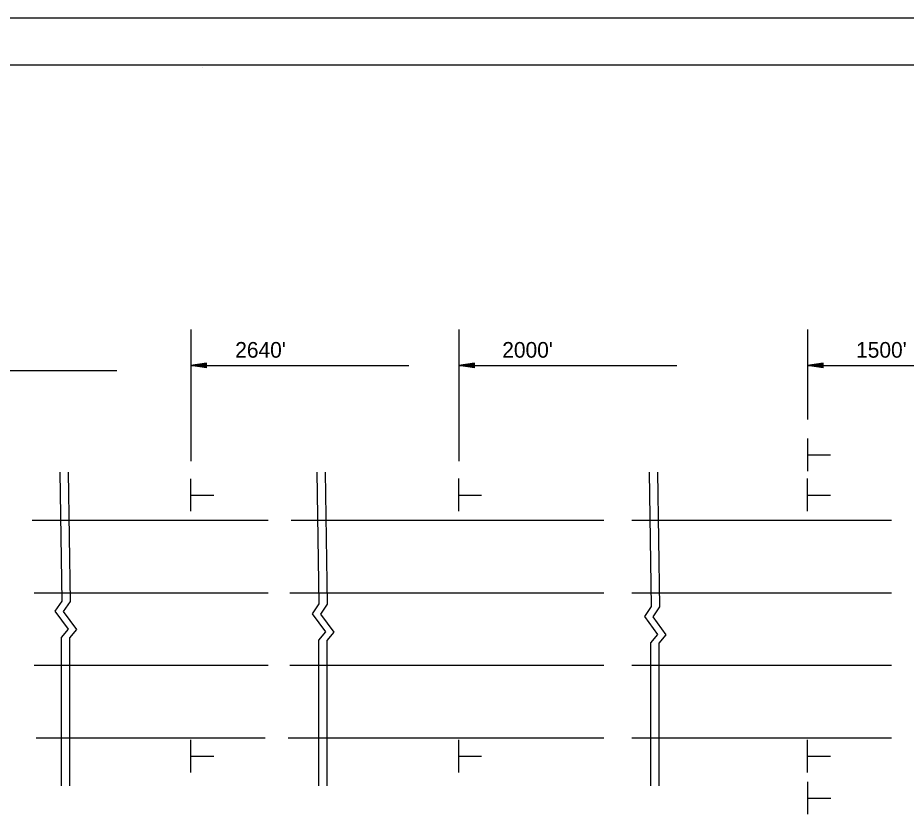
# Model space of a CAD drawing. Extents: x 1397271 to 1411271, y 376395 to 377888.
# Drawn here: x 1402985 to 1403500, y 377424 to 377888 of the extents above; entities that cross this region are included whole.
import ezdxf

# ---------------------------------------------------------------- set-up
doc = ezdxf.new("R2010")
doc.units = 0
for name, color, linetype in [('Default', 7, 'Continuous'), ('R_Border', 7, 'Continuous'), ('R_MOT', 7, 'Continuous'), ('R_No Plot', 7, 'Continuous')]:
    doc.layers.add(name, color=color, linetype=linetype)

msp = doc.modelspace()

# ---------------------------------------------------------------- linework, layer by layer
at = {"layer": 'Default'}
for p, q in [((1403085.35, 377707.31), (1403085.35, 377631.08)), ((1403240.48, 377707.31), (1403240.48, 377631.08)), ((1403442.43, 377707.31), (1403442.43, 377655.12)), ((1403094.42, 377687.9), (1403085.35, 377686.54)), ((1403094.42, 377687.67), (1403086.87, 377686.54)), ((1403094.42, 377687.44), (1403088.43, 377686.54)), ((1403094.42, 377687.22), (1403089.94, 377686.54)), ((1403094.42, 377686.98), (1403091.47, 377686.54)), ((1403094.42, 377685.18), (1403094.42, 377687.9)), ((1403249.55, 377687.9), (1403240.48, 377686.54)), ((1403249.55, 377687.67), (1403242, 377686.54)), ((1403249.55, 377687.44), (1403243.56, 377686.54)), ((1403249.55, 377687.22), (1403245.07, 377686.54)), ((1403249.55, 377686.98), (1403246.6, 377686.54)), ((1403249.55, 377685.18), (1403249.55, 377687.9)), ((1403451.5, 377687.9), (1403442.43, 377686.54)), ((1403451.5, 377687.67), (1403443.95, 377686.54)), ((1403451.5, 377687.44), (1403445.51, 377686.54)), ((1403451.5, 377687.22), (1403447.02, 377686.54)), ((1403451.5, 377686.98), (1403448.55, 377686.54)), ((1403451.5, 377685.18), (1403451.5, 377687.9)), ((1402916.19, 377683.64), (1403042.37, 377683.64)), ((1403085.35, 377686.54), (1403211.54, 377686.54)), ((1403094.42, 377685.18), (1403085.35, 377686.54)), ((1403094.42, 377685.41), (1403086.87, 377686.54)), ((1403094.42, 377685.64), (1403088.43, 377686.54)), ((1403094.42, 377685.86), (1403089.94, 377686.54)), ((1403094.42, 377686.1), (1403091.47, 377686.54)), ((1403094.42, 377686.75), (1403092.99, 377686.54)), ((1403094.42, 377686.33), (1403092.99, 377686.54)), ((1403240.48, 377686.54), (1403366.67, 377686.54)), ((1403249.55, 377685.18), (1403240.48, 377686.54)), ((1403249.55, 377685.41), (1403242, 377686.54)), ((1403249.55, 377685.64), (1403243.56, 377686.54)), ((1403249.55, 377685.86), (1403245.07, 377686.54)), ((1403249.55, 377686.1), (1403246.6, 377686.54)), ((1403249.55, 377686.75), (1403248.12, 377686.54)), ((1403249.55, 377686.33), (1403248.12, 377686.54)), ((1403442.43, 377686.54), (1403568.62, 377686.54)), ((1403451.5, 377685.18), (1403442.43, 377686.54)), ((1403451.5, 377685.41), (1403443.95, 377686.54)), ((1403451.5, 377685.64), (1403445.51, 377686.54)), ((1403451.5, 377685.86), (1403447.02, 377686.54)), ((1403451.5, 377686.1), (1403448.55, 377686.54)), ((1403451.5, 377686.75), (1403450.07, 377686.54)), ((1403451.5, 377686.33), (1403450.07, 377686.54)), ((1402993.52, 377596.8), (1403130.05, 377596.8)), ((1403143.36, 377596.8), (1403324.47, 377596.8)), ((1403340.61, 377596.8), (1403491.05, 377596.8)), ((1402994.63, 377554.76), (1403130.05, 377554.76)), ((1403142.54, 377554.76), (1403324.47, 377554.76)), ((1403340.61, 377554.76), (1403491.05, 377554.76)), ((1402994.63, 377512.73), (1403130.05, 377512.73)), ((1403142.54, 377512.73), (1403324.47, 377512.73)), ((1403340.61, 377512.73), (1403491.05, 377512.73)), ((1402995.74, 377470.69), (1403128.42, 377470.69)), ((1403141.73, 377470.69), (1403324.47, 377470.69)), ((1403340.61, 377470.69), (1403491.05, 377470.69))]:
    msp.add_line(p, q, dxfattribs=at)
at = {"layer": 'R_Border'}
for p, q in [((1402024.58, 377860.72), (1404237.88, 377860.72)), ((1403092.23, 377858.9), (1403092.23, 377858.9)), ((1403092.23, 377858.9), (1403092.23, 377858.9))]:
    msp.add_line(p, q, dxfattribs=at)
at = {"layer": 'R_MOT'}
for p, q in [((1403442.48, 377625.33), (1403442.48, 377644.24)), ((1403442.76, 377634.73), (1403455.67, 377634.73)), ((1403085.35, 377601.98), (1403085.35, 377620.89)), ((1403240.48, 377601.98), (1403240.48, 377620.9)), ((1403442.43, 377601.98), (1403442.43, 377620.9)), ((1403085.63, 377611.39), (1403098.54, 377611.39)), ((1403240.76, 377611.39), (1403253.67, 377611.39)), ((1403442.71, 377611.39), (1403455.63, 377611.39)), ((1403085.35, 377450.7), (1403085.35, 377469.62)), ((1403240.48, 377450.7), (1403240.48, 377469.62)), ((1403442.43, 377450.7), (1403442.43, 377469.62)), ((1403085.63, 377460.11), (1403098.54, 377460.11)), ((1403240.76, 377460.11), (1403253.67, 377460.11)), ((1403442.71, 377460.11), (1403455.63, 377460.11)), ((1403442.64, 377426.4), (1403442.64, 377445.31)), ((1403442.92, 377435.8), (1403455.83, 377435.8))]:
    msp.add_line(p, q, dxfattribs=at)
for points in [[(1403009.37, 377624.62), (1403010.51, 377549.98), (1403006.58, 377544.14), (1403014.23, 377533.67), (1403010.2, 377528.84), (1403010.18, 377442.87)], [(1403014.2, 377624.62), (1403015.34, 377549.78), (1403011.41, 377543.94), (1403019.06, 377533.47), (1403015.03, 377528.64), (1403015.02, 377442.87)], [(1403158.3, 377624.62), (1403159.46, 377548.39), (1403155.54, 377542.55), (1403163.19, 377532.09), (1403159.16, 377527.25), (1403159.15, 377442.87)], [(1403163.13, 377624.62), (1403164.29, 377548.19), (1403160.37, 377542.35), (1403168.02, 377531.89), (1403163.99, 377527.05), (1403163.98, 377442.87)], [(1403350.66, 377624.62), (1403351.84, 377546.87), (1403347.91, 377541.03), (1403355.56, 377530.56), (1403351.54, 377525.73), (1403351.52, 377442.87)], [(1403355.49, 377624.62), (1403356.67, 377546.67), (1403352.74, 377540.83), (1403360.39, 377530.36), (1403356.37, 377525.53), (1403356.35, 377442.87)]]:
    msp.add_lwpolyline(points, dxfattribs=at)
at = {"layer": 'R_No Plot'}
msp.add_line((1401937.77, 377887.98), (1404271.14, 377887.98), dxfattribs=at)
for points in [[(1401937.72, 377887.98), (1404271.14, 377887.98), (1404271.14, 376394.59), (1401937.72, 376394.59)], [(1403662.05, 377860.72), (1403662.05, 377791.56), (1403912.17, 377791.56), (1403912.17, 377771.12), (1404074.57, 377771.12), (1404074.57, 377600.79), (1404237.88, 377600.79), (1404237.88, 376422.47), (1402024.58, 376422.47), (1402024.58, 377860.72)]]:
    msp.add_lwpolyline(points, close=True, dxfattribs=at)

# ---------------------------------------------------------------- texts
at = {"layer": 'Default'}
for s, p in [("2640'", (1403110.99, 377691.01)), ("2000'", (1403265.62, 377691.01)), ("1500'", (1403470.5, 377691.01))]:
    msp.add_text(s, height=9.067, dxfattribs=at).set_placement(p)

doc.saveas('drawing.dxf')
